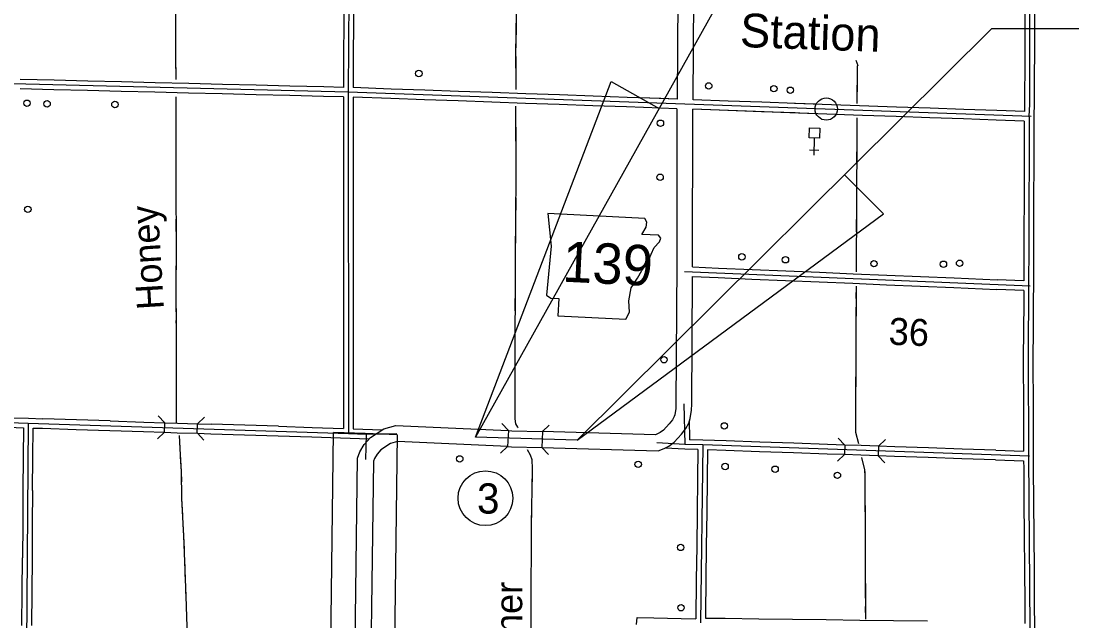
# Model space of a CAD drawing. Extents: x -4306 to 3843, y 131 to 8053.
# Drawn here: x -251 to 2383, y 4853 to 6356 of the extents above; entities that cross this region are included whole.
import ezdxf

# ---------------------------------------------------------------- set-up
doc = ezdxf.new("R2010")
doc.units = 0
for name, color, linetype in [('10', 7, 'Continuous'), ('21', 7, 'Continuous'), ('24', 7, 'Continuous'), ('31', 7, 'Continuous'), ('32', 7, 'Continuous'), ('37', 7, 'Continuous'), ('38', 7, 'Continuous'), ('43', 7, 'Continuous'), ('46', 7, 'Continuous'), ('5', 7, 'Continuous'), ('56', 7, 'Continuous'), ('57', 7, 'Continuous'), ('6', 7, 'Continuous'), ('R_No Plot', 7, 'Continuous')]:
    doc.layers.add(name, color=color, linetype=linetype)

msp = doc.modelspace()

# ---------------------------------------------------------------- linework, layer by layer
at = {"layer": '10'}
for p, q in [((1398.6, 6820.3), (1393.1, 6160.5)), ((1433.1, 6159.1), (1438.6, 6819.9)), ((1392.8, 6136.5), (1392.1, 5747.2)), ((1432, 5740.1), (1432.8, 6135.1)), ((1392.1, 5747.2), (1389.9, 5397.2)), ((1429.9, 5396.7), (1431.9, 5716.1)), ((1389.7, 5385.2), (1387.2, 5370.1)), ((1389.9, 5397.2), (1389.7, 5385.2)), ((1426.2, 5360.4), (1429.6, 5381.7)), ((1429.6, 5381.7), (1429.9, 5396.7)), ((1373.5, 5347), (1358.8, 5331.4)), ((1381.2, 5357.3), (1373.5, 5347)), ((1385.6, 5365.4), (1381.2, 5357.3)), ((1387.2, 5370.1), (1385.6, 5365.4)), ((1414.9, 5335.6), (1422.4, 5349.1)), ((1422.4, 5349.1), (1426.2, 5360.4)), ((970.3, 5330.2), (968.5, 5290.2)), ((970.2, 5330.2), (979.3, 5329.8)), ((979.3, 5329.8), (1055.4, 5327.7)), ((1055.5, 5327.7), (1054.4, 5287.7)), ((1338.9, 5319.9), (1055.4, 5327.7)), ((1344, 5321.7), (1338.9, 5319.9)), ((1350.7, 5325.3), (1344, 5321.7)), ((1358.8, 5331.4), (1350.7, 5325.3)), ((1385.6, 5301.5), (1404.2, 5321.2)), ((1404.2, 5321.2), (1414.9, 5335.6)), ((1372.3, 5291.4), (1385.6, 5301.5)), ((968.7, 5290.2), (977.9, 5289.8)), ((977.9, 5289.8), (1054.1, 5287.7)), ((1054.1, 5287.7), (1345.4, 5279.7)), ((1345.4, 5279.7), (1360.3, 5285.1)), ((1360.3, 5285.1), (1372.3, 5291.4))]:
    msp.add_line(p, q, dxfattribs=at)
for points in [[(581.8, 4463.7), (592.6, 5261.1), (598.4, 5277.4), (608.7, 5295.2), (624.9, 5312.8), (658.1, 5334.6), (688.3, 5342.8), (970.2, 5330.2)], [(968.7, 5290.2), (692.8, 5302.6), (674.8, 5297.7), (651, 5282.1), (641.1, 5271.4), (634.9, 5260.6), (632.5, 5254), (621.8, 4462.2)]]:
    msp.add_lwpolyline(points, dxfattribs=at)
at = {"layer": '21'}
msp.add_lwpolyline([(1069, 5873.9), (1077.2, 5792.2), (1065.8, 5669.4), (1076.3, 5662.1), (1096.6, 5661.2), (1094.5, 5617.9), (1264.8, 5609.6), (1273.8, 5626.7), (1272.5, 5655.3), (1278.1, 5687.5), (1294.2, 5712.5), (1304.6, 5730.9), (1319.1, 5750.6), (1328.3, 5771.8), (1335.9, 5789), (1348.8, 5803.3), (1352, 5812.6), (1346.9, 5819.7), (1305, 5821.7), (1315.4, 5840.2), (1317.3, 5852.3), (1312.2, 5861.9)], close=True, dxfattribs=at)
at = {"layer": '24'}
msp.add_circle((1766.9, 6135.8), 28, dxfattribs=at)
at = {"layer": '31'}
for p, q in [((-269.5, 5362), (-232.4, 5361)), ((-232.4, 5361), (-196.6, 5359.9)), ((-27.7, 5354.4), (56.7, 5351.7)), ((56.7, 5351.7), (109.5, 5350)), ((108.8, 5326.1), (109.5, 5350.1)), ((109.5, 5350), (141.2, 5349)), ((141.2, 5349), (191.7, 5347.4)), ((190.7, 5323.4), (191.5, 5347.4)), ((191.7, 5347.4), (225.6, 5346.3)), ((-281.8, 5338.4), (-244.9, 5337.3)), ((-220.9, 5336.6), (-197.4, 5335.9)), ((-28.5, 5330.4), (56, 5327.7)), ((56, 5327.7), (108.5, 5326)), ((108.5, 5326), (140.4, 5325)), ((140.4, 5325), (190.9, 5323.4)), ((190.9, 5323.4), (224.9, 5322.3)), ((394.5, 5340.9), (479, 5338.1)), ((479, 5338.1), (557.4, 5335.6)), ((581.4, 5334.9), (653.8, 5332.5)), ((393.7, 5316.9), (478.2, 5314.2)), ((478.2, 5314.2), (621.8, 5309.5)), ((-246.1, 5180.1), (-246.7, 5095.6)), ((-222.1, 5179.9), (-222.7, 5095.5)), ((-246.7, 5095.6), (-247.3, 5011.2)), ((-222.7, 5095.5), (-223.3, 5011))]:
    msp.add_line(p, q, dxfattribs=at)
for points in [[(-112.2, 5357.1), (-196.6, 5359.9)], [(-27.7, 5354.4), (-112.2, 5357.1)], [(310.1, 5343.6), (225.6, 5346.3)], [(-244.9, 5337.3), (-245.4, 5264.6)], [(-221.4, 5264.4), (-220.9, 5336.6)], [(-197.4, 5335.9), (-112.9, 5333.2)], [(-112.9, 5333.2), (-28.5, 5330.4)], [(224.9, 5322.3), (309.3, 5319.6)], [(394.5, 5340.9), (310.1, 5343.6)], [(309.3, 5319.6), (393.7, 5316.9)], [(-245.4, 5264.6), (-246.1, 5180.1)], [(-222.1, 5179.9), (-221.4, 5264.4)], [(-248, 4926.7), (-247.3, 5011.2)], [(-223.3, 5011), (-224, 4926.5)], [(-248.6, 4842.2), (-248, 4926.7)], [(-224, 4926.5), (-224.6, 4842)]]:
    msp.add_lwpolyline(points, dxfattribs=at)
at = {"layer": '32'}
for p, q in [((573.1, 7028.1), (569.1, 6177.8)), ((2276.5, 6530), (2276.2, 6245.5)), ((2276.5, 6530), (2276.2, 6245.5)), ((558.3, 6436.7), (557.9, 6352.2)), ((582.3, 6436.6), (581.9, 6352.1)), ((2264.4, 6418.9), (2264.3, 6334.5)), ((2288.4, 6418.9), (2288.3, 6334.4)), ((557.9, 6352.2), (557.5, 6267.8)), ((581.9, 6352.1), (581.5, 6267.6)), ((2264.3, 6334.5), (2264.2, 6250)), ((2288.3, 6334.4), (2288.3, 6249.9)), ((557.5, 6267.8), (557.1, 6190.1)), ((581.5, 6267.6), (581.1, 6189.4)), ((2264.2, 6245.5), (2264, 6165.5)), ((2264.2, 6250), (2264.2, 6245.5)), ((2276.2, 6245.5), (2276, 6146.8)), ((2276.2, 6245.5), (2276, 6146.8)), ((2288.2, 6245.5), (2288, 6165.4)), ((2288.3, 6249.9), (2288.2, 6245.5)), ((569.1, 6177.8), (-271.9, 6198.6)), ((-168.2, 6208), (-252.7, 6210.1)), ((-83.8, 6205.9), (-168.2, 6208)), ((0.7, 6203.8), (-83.8, 6205.9)), ((85.2, 6201.7), (0.7, 6203.8)), ((169.6, 6199.7), (85.2, 6201.7)), ((254.1, 6197.6), (169.6, 6199.7)), ((338.6, 6195.5), (254.1, 6197.6)), ((423, 6193.4), (338.6, 6195.5)), ((507.5, 6191.3), (423, 6193.4)), ((557.1, 6190.1), (507.5, 6191.3)), ((676.5, 6186), (581.1, 6189.4)), ((-168.8, 6184), (-253.3, 6186.1)), ((-84.4, 6181.9), (-168.8, 6184)), ((0.1, 6179.8), (-84.4, 6181.9)), ((84.6, 6177.7), (0.1, 6179.8)), ((169, 6175.7), (84.6, 6177.7)), ((253.5, 6173.6), (169, 6175.7)), ((338, 6171.5), (253.5, 6173.6)), ((422.4, 6169.4), (338, 6171.5)), ((506.9, 6167.3), (422.4, 6169.4)), ((557.1, 6166.1), (506.9, 6167.3)), ((557.1, 6166.1), (557.1, 6098.7)), ((569.1, 6177.8), (569.4, 5323.2)), ((2280.4, 6116.9), (569.1, 6177.8)), ((581.1, 6165.3), (581.1, 6098.7)), ((675.7, 6162), (581.1, 6165.3)), ((760.9, 6183), (676.5, 6186)), ((845.4, 6180), (760.9, 6183)), ((929.8, 6177), (845.4, 6180)), ((1014.2, 6174), (929.8, 6177)), ((1098.7, 6171), (1014.2, 6174)), ((1183.1, 6168), (1098.7, 6171)), ((1267.6, 6164.9), (1183.1, 6168)), ((1352, 6161.9), (1267.6, 6164.9)), ((1393.1, 6160.5), (1302, 6163.7)), ((1393.1, 6160.5), (1302, 6163.7)), ((2264, 6165.5), (2264, 6129.7)), ((2288, 6165.4), (2288, 6146.5)), ((760.1, 6159), (675.7, 6162)), ((844.5, 6156), (760.1, 6159)), ((929, 6153), (844.5, 6156)), ((1013.4, 6150), (929, 6153)), ((1097.8, 6147), (1013.4, 6150)), ((1182.3, 6144), (1097.8, 6147)), ((1266.7, 6141), (1182.3, 6144)), ((1351.1, 6138), (1266.7, 6141)), ((1392.8, 6136.5), (1351.1, 6138)), ((1393.1, 6160.5), (1352, 6161.9)), ((1520.9, 6155.9), (1433.1, 6159.1)), ((1605.3, 6152.9), (1520.9, 6155.9)), ((1689.7, 6149.9), (1605.3, 6152.9)), ((1943, 6140.9), (1687.3, 6150)), ((1741.7, 6148.1), (1687.3, 6150)), ((2027.5, 6137.9), (1943, 6140.9)), ((2111.9, 6134.9), (2027.5, 6137.9)), ((2276, 6146.8), (2274.8, 6117.7)), ((2276, 6146.8), (2274.8, 6117.7)), ((2288, 6146.5), (2287, 6121.8)), ((1741.5, 6124.1), (1432.8, 6135.1)), ((1857.8, 6119.9), (1432.8, 6135.1)), ((1520, 6132), (1432.8, 6135.1)), ((1604.4, 6128.9), (1520, 6132)), ((1688.9, 6125.9), (1604.4, 6128.9)), ((1942.2, 6116.9), (1857.8, 6119.9)), ((2026.6, 6113.9), (1942.2, 6116.9)), ((2111.1, 6110.9), (2026.6, 6113.9)), ((2192.5, 6108.2), (2111.1, 6110.9)), ((2194.1, 6132.2), (2111.9, 6134.9)), ((2264, 6129.7), (2194, 6132.2)), ((2275, 6114), (2274.1, 5793.5)), ((2275, 6114), (2274.1, 5793.5)), ((2274.8, 6117.7), (2275, 6114)), ((2274.8, 6117.7), (2275, 6114)), ((2287, 6121.8), (2286.9, 6081)), ((557.1, 6098.7), (557.1, 6014.2)), ((581.1, 6098.7), (581.1, 6014.2)), ((2262.9, 6105.7), (2192.6, 6108.3)), ((2262.9, 6105.7), (2262.7, 5996.6)), ((2286.9, 6081), (2286.7, 5996.5)), ((557.1, 6014.2), (557.2, 5929.7)), ((581.1, 6014.2), (581.2, 5929.7)), ((2262.7, 5996.6), (2262.4, 5912.1)), ((2286.7, 5996.5), (2286.4, 5912)), ((557.2, 5929.7), (557.2, 5845.2)), ((581.2, 5929.7), (581.2, 5845.3)), ((2262.4, 5912.1), (2262.2, 5827.6)), ((2286.4, 5912), (2286.2, 5827.5)), ((557.2, 5845.2), (557.2, 5760.8)), ((581.2, 5845.3), (581.3, 5760.8)), ((2262.2, 5827.6), (2262.1, 5793.5)), ((2286.2, 5827.5), (2286.1, 5793.5)), ((2262.1, 5793.5), (2262, 5743.1)), ((2274.1, 5793.5), (2273.8, 5693.1)), ((2274.1, 5793.5), (2273.8, 5693.1)), ((2286.1, 5793.5), (2286, 5743)), ((557.2, 5760.8), (557.3, 5676.3)), ((581.3, 5760.8), (581.3, 5676.3)), ((2262, 5743.1), (2261.9, 5705.1)), ((2286, 5743), (2285.8, 5693.1)), ((1411.9, 5728.9), (2278.2, 5692.6)), ((1431.9, 5716.1), (1495.8, 5713.4)), ((1432, 5740.1), (1496.8, 5737.4)), ((1496.8, 5737.4), (1581.2, 5733.8)), ((1581.2, 5733.8), (1665.6, 5730.3)), ((1665.6, 5730.3), (1750.1, 5726.8)), ((1750.1, 5726.8), (1834.5, 5723.2)), ((1834.5, 5723.2), (1918.9, 5719.7)), ((1918.9, 5719.7), (2003.3, 5716.1)), ((2003.3, 5716.1), (2087.7, 5712.6)), ((1495.8, 5713.4), (1580.2, 5709.9)), ((1580.2, 5709.9), (1664.6, 5706.3)), ((1664.6, 5706.3), (1749.1, 5702.8)), ((1749.1, 5702.8), (1833.5, 5699.2)), ((1833.5, 5699.2), (1917.9, 5695.7)), ((1917.9, 5695.7), (2002.3, 5692.2)), ((2002.3, 5692.2), (2086.7, 5688.6)), ((2086.7, 5688.6), (2194.4, 5683.9)), ((2087.7, 5712.6), (2195.4, 5707.9)), ((2261.9, 5705.1), (2195.4, 5707.9)), ((2273.8, 5693.1), (2272.6, 5518.6)), ((2273.8, 5693.1), (2272.6, 5518.6)), ((2285.8, 5693.1), (2285.6, 5658.5)), ((557.3, 5676.3), (557.3, 5591.8)), ((581.3, 5676.3), (581.3, 5591.8)), ((2261.8, 5681.1), (2194.4, 5683.9)), ((2261.8, 5681.1), (2261.6, 5658.6)), ((2261.6, 5658.6), (2261, 5574.2)), ((2285.6, 5658.5), (2285, 5574)), ((557.3, 5591.8), (557.4, 5507.3)), ((581.3, 5591.8), (581.4, 5507.3)), ((2261, 5574.2), (2260.6, 5518.6)), ((2285, 5574), (2284.6, 5518.6)), ((557.4, 5507.3), (557.4, 5422.8)), ((581.4, 5507.3), (581.4, 5422.8)), ((2260.6, 5518.6), (2260.7, 5489.6)), ((2272.6, 5518.6), (2273.4, 5266)), ((2272.6, 5518.6), (2273.4, 5266)), ((2284.6, 5518.6), (2284.7, 5489.6)), ((2260.7, 5489.6), (2261, 5405.1)), ((2284.7, 5489.6), (2285, 5405.1)), ((557.4, 5422.8), (557.4, 5335.6)), ((581.4, 5422.8), (581.4, 5334.9)), ((2261, 5405.1), (2261.2, 5320.6)), ((2285, 5405.1), (2285.2, 5320.7)), ((1409.9, 5396.9), (1412.9, 5295.6)), ((-281.4, 5350.4), (-232.8, 5349)), ((-232.8, 5349), (-239.3, 4486.5)), ((-232.8, 5349), (569.4, 5323.2)), ((1423.2, 5352.9), (1424.4, 5312.8)), ((569.4, 5323.2), (613.9, 5321.6)), ((613.9, 5321.6), (612.6, 5257.5)), ((613.9, 5321.6), (690.6, 5322.7)), ((2261.2, 5320.6), (2261.4, 5278.7)), ((2285.2, 5320.7), (2285.4, 5266.1)), ((1412.9, 5295.6), (1342.1, 5299.8)), ((1457.4, 5294.3), (1412.9, 5295.6)), ((1424.4, 5312.8), (1424.6, 5307.2)), ((1457.8, 5306.3), (1424.6, 5307.2)), ((1457.4, 5294.3), (1451.8, 4848.8)), ((2275.9, 5266), (1457.4, 5294.3)), ((1516.4, 5304.2), (1457.8, 5306.2)), ((1600.8, 5301.3), (1516.4, 5304.2)), ((1685.3, 5298.4), (1600.8, 5301.3)), ((1769.7, 5295.5), (1685.3, 5298.4)), ((1813.2, 5294), (1769.7, 5295.5)), ((1813.2, 5294), (1812.3, 5270)), ((1854.1, 5292.6), (1813.2, 5294)), ((1412.4, 5283.6), (1362.9, 5286.5)), ((1445.3, 5282.6), (1412.4, 5283.6)), ((1445.3, 5282.6), (1444.4, 5209.9)), ((1469.3, 5281.8), (1468.4, 5209.6)), ((1515.5, 5280.2), (1469.3, 5281.8)), ((1600, 5277.3), (1515.5, 5280.2)), ((1684.4, 5274.4), (1600, 5277.3)), ((1768.9, 5271.5), (1684.4, 5274.4)), ((1812.3, 5270), (1768.9, 5271.5)), ((1853.3, 5268.6), (1812.3, 5270)), ((1897.3, 5267.1), (1853.3, 5268.6)), ((1898.1, 5291.1), (1854.1, 5292.6)), ((1898.1, 5291.1), (1897.3, 5267.1)), ((1938.6, 5289.7), (1898.1, 5291.1)), ((2023, 5286.7), (1938.6, 5289.7)), ((2107.4, 5283.8), (2023, 5286.7)), ((2191.8, 5281.1), (2107.4, 5283.8)), ((2191.8, 5281.1), (2261.4, 5278.7)), ((1937.7, 5265.7), (1897.3, 5267.1)), ((2022.2, 5262.8), (1937.7, 5265.7)), ((2106.6, 5259.8), (2022.2, 5262.8)), ((2191, 5257.2), (2106.6, 5259.8)), ((2191, 5257.2), (2261.5, 5254.7)), ((2261.5, 5254.7), (2261.6, 5236)), ((2273.4, 5266), (2276.7, 4834.6)), ((2273.4, 5266), (2276.7, 4834.6)), ((2285.4, 5266.1), (2285.6, 5236.2)), ((2261.6, 5236), (2262.3, 5151.5)), ((2285.6, 5236.2), (2286.3, 5151.7)), ((1444.4, 5209.9), (1443.3, 5125.4)), ((1468.4, 5209.6), (1467.3, 5125.1)), ((2262.3, 5151.5), (2262.9, 5067.1)), ((2286.3, 5151.7), (2286.9, 5067.2)), ((1443.3, 5125.4), (1442.2, 5041)), ((1467.3, 5125.1), (1466.2, 5040.7)), ((2262.9, 5067.1), (2263.6, 4982.6)), ((2286.9, 5067.2), (2287.6, 4982.8)), ((1442.2, 5041), (1441.1, 4956.5)), ((1466.2, 5040.7), (1465.1, 4956.2)), ((2263.6, 4982.6), (2264.2, 4898.1)), ((2287.6, 4982.8), (2288.2, 4898.3)), ((1441.1, 4956.5), (1439.9, 4858.8)), ((1465.1, 4956.2), (1464.1, 4871.7)), ((2264.2, 4898.1), (2264.6, 4846.6)), ((2288.2, 4898.3), (2288.7, 4834.6)), ((1464.1, 4871.7), (1463.9, 4860.6)), ((1463.9, 4860.6), (1513.3, 4859.9)), ((1513.3, 4859.9), (1597.8, 4858.8)), ((1597.8, 4858.8), (1682.3, 4857.7)), ((1682.3, 4857.7), (1766.8, 4856.6)), ((1766.8, 4856.6), (1851.2, 4855.5)), ((1851.2, 4855.5), (1935.7, 4854.4)), ((1935.7, 4854.4), (2020.2, 4853.2))]:
    msp.add_line(p, q, dxfattribs=at)
at = {"layer": '37'}
for p, q in [((969.4, 5310.2), (969.4, 5310.2)), ((1054.9, 5307.7), (1054.9, 5307.7))]:
    msp.add_line(p, q, dxfattribs=at)
for points in [[(970.3, 5330.2), (954.1, 5347.9)], [(1072.9, 5344.2), (1055.5, 5327.7)], [(950.8, 5274), (968.5, 5290.2)], [(1054.4, 5287.7), (1070.9, 5270.2)]]:
    msp.add_lwpolyline(points, dxfattribs=at)
at = {"layer": '38'}
for points in [[(92.9, 5367.5), (109.3, 5350)], [(191.7, 5347.4), (209.2, 5363.8)], [(108.5, 5326), (91, 5309.6)], [(207.3, 5305.9), (190.9, 5323.4)], [(1796.8, 5311.5), (1813.2, 5294)], [(1898.1, 5291.1), (1915.6, 5307.5)], [(1812.3, 5270), (1794.8, 5253.6)], [(1913.7, 5249.5), (1897.3, 5267.1)]]:
    msp.add_lwpolyline(points, dxfattribs=at)
at = {"layer": '43'}
for points in [[(137, 7010.5), (136.7, 6978.4), (137.2, 6875.4), (136.8, 6800.3), (136.9, 6727.5), (136.9, 6612.5), (136.7, 6457.1), (136.1, 6359.3), (136, 6263.3), (137.2, 6210)], [(990.8, 6996.5), (990.7, 6986.2), (991, 6793.8), (990.1, 6688.9), (989.1, 6602.1), (990.1, 6491.2), (989.9, 6377.6), (988.5, 6273.2), (989.3, 6201.9), (988.9, 6184.6)], [(136.1, 6366.2), (136.1, 6359.3), (136, 6302.9)], [(989.6, 6352.3), (988.7, 6288.9)], [(136, 6281.7), (136, 6263.3), (137, 6218.4)], [(988.6, 6267.8), (989.3, 6204.4)], [(1841.2, 6258.1), (1845.8, 6244.8), (1844.7, 6243.1), (1843.9, 6149.8)], [(1841.2, 6258.1), (1845.8, 6244.8), (1844.7, 6243.1), (1844.5, 6227.5)], [(1844.4, 6206.3), (1843.9, 6149.8)], [(137.2, 6166.1), (137.1, 6057.3), (136.7, 5955.8), (137.5, 5782.3), (136.8, 5681.7), (137.5, 5591.2), (138.2, 5550.4), (138, 5431.7), (137.9, 5349.1)], [(137.2, 6166.1), (137.1, 6134.5)], [(988.4, 6143.3), (989.1, 5966.3)], [(988.4, 6143.3), (988.5, 6111.6)], [(137.1, 6113.3), (137.1, 6057.3), (137, 6050)], [(1843.6, 6113.5), (1843.2, 6070.2), (1841.7, 5727.9)], [(1843.6, 6113.5), (1843.3, 6081.8)], [(988.6, 6090.5), (988.9, 6027.1)], [(1843.2, 6060.7), (1842.9, 5997.3)], [(137, 6028.8), (136.8, 5965.5)], [(988.9, 6006), (989.1, 5966.3)], [(989.1, 5966.3), (987.4, 5768.6), (987.2, 5746.5)], [(989.1, 5966.3), (988.8, 5934.6)], [(1842.8, 5976.2), (1842.5, 5912.8)], [(136.8, 5944.4), (137.1, 5881)], [(988.6, 5913.5), (988.1, 5850.1)], [(1842.4, 5891.7), (1842.2, 5828.3)], [(137.2, 5859.9), (137.5, 5796.5)], [(987.9, 5829), (987.4, 5768.6), (987.3, 5765.7)], [(1842.1, 5807.2), (1841.8, 5743.8)], [(137.5, 5775.4), (137, 5712)], [(987.2, 5746.5), (986.2, 5491.9), (986.4, 5359.4), (988, 5347.3), (992.9, 5338.6), (993.9, 5336.8)], [(987.2, 5746.5), (987, 5714.8)], [(136.9, 5690.9), (136.8, 5681.7), (137, 5659.2)], [(987, 5693.7), (986.7, 5630.4)], [(1841.6, 5692.4), (1840.2, 5389.5), (1840.4, 5326.3), (1847.8, 5298.2)], [(1841.6, 5692.4), (1841.4, 5660.8)], [(137, 5659.2), (137.2, 5627.5)], [(1841.3, 5639.6), (1841.1, 5576.3)], [(137.3, 5606.4), (137.5, 5591.2), (138.2, 5550.4), (138.2, 5543)], [(986.6, 5609.2), (986.4, 5545.9)], [(1841, 5555.2), (1840.7, 5491.8)], [(138.2, 5521.9), (138.1, 5458.6)], [(986.3, 5524.7), (986.2, 5491.9), (986.2, 5461.4)], [(1840.6, 5470.7), (1840.3, 5407.3)], [(138, 5437.4), (138, 5431.7), (137.9, 5374.1)], [(986.2, 5440.3), (986.3, 5376.9)], [(1840.2, 5386.2), (1840.4, 5326.3), (1841.3, 5322.9)], [(145, 5317.6), (147, 5284.2), (150.3, 5227.5), (151.6, 5159.7), (156.3, 5066.2), (161.9, 4915.7), (165.2, 4812.6), (170.9, 4701), (174.9, 4602.5), (179.8, 4480.8)], [(145, 5317.6), (146.9, 5285.9)], [(1017.4, 5282.9), (1025.1, 5269.5), (1029.4, 5258.2), (1029.6, 5234.1), (1027.7, 5087.5), (1026.4, 4887), (1026.8, 4858.6), (1022.2, 4580.9), (1020.1, 4448.8)], [(1017.4, 5282.9), (1025.1, 5269.5), (1029.4, 5258.2), (1029.5, 5254)], [(148.1, 5264.9), (150.3, 5227.5), (150.8, 5201.6)], [(1865.8, 4857.8), (1864.5, 5216.2), (1863.8, 5232), (1856.4, 5262.8)], [(1029.6, 5232.9), (1028.8, 5169.6)], [(1864.7, 5164), (1864.5, 5216.2), (1864, 5227.4)], [(151.2, 5180.4), (151.6, 5159.7), (153.7, 5117.1)], [(1028.5, 5148.4), (1027.7, 5087.5), (1027.7, 5085.1)], [(1865, 5079.5), (1864.8, 5142.9)], [(154.8, 5096), (156.3, 5066.2), (157.6, 5032.7)], [(1027.6, 5064), (1027.2, 5000.6)], [(1865.3, 4995.1), (1865.1, 5058.4)], [(158.3, 5011.6), (160.7, 4948.3)], [(1027, 4979.5), (1026.6, 4916.1)], [(1865.6, 4910.6), (1865.4, 4973.9)], [(161.5, 4927.2), (161.9, 4915.7), (163.6, 4863.9)], [(1026.4, 4895), (1026.4, 4887), (1026.8, 4858.6), (1026.3, 4831.6)], [(1865.8, 4857.8), (1865.6, 4889.4)]]:
    msp.add_lwpolyline(points, dxfattribs=at)
at = {"layer": '46'}
for p, q in [((1291.7, 4844.6), (1293.3, 4862)), ((1293.3, 4862), (1334.8, 4860.9)), ((1334.8, 4860.9), (1403.3, 4859.2)), ((1403.3, 4859.2), (1439.9, 4858.8))]:
    msp.add_line(p, q, dxfattribs=at)
at = {"layer": '56'}
for centre in [(745.9, 6224.9), (1472.4, 6193.7), (1635.6, 6186.9), (1676.8, 6183), (-236, 6150.4), (-185.7, 6148.8), (-15.6, 6147.2), (1351.3, 6100.3), (1350.6, 5964.9), (-233.9, 5884.5), (1555.4, 5765.5), (1664.6, 5758.2), (1886.5, 5748.5), (2060.5, 5747), (2101, 5749.4), (1360.3, 5507.7), (1511.4, 5342), (848.4, 5259.3), (1295.6, 5245.6), (1513.4, 5240.3), (1638.7, 5233.4), (1794.8, 5218.2), (1402.1, 5037.5), (1402.9, 4886.4)]:
    msp.add_circle(centre, 8, dxfattribs=at)
at = {"layer": '57'}
for p, q in [((1736.3, 6020.2), (1737.1, 6063.2)), ((1748.5, 6031.9), (1724.5, 6032.4))]:
    msp.add_line(p, q, dxfattribs=at)
msp.add_lwpolyline([(1750.5, 6088), (1750.1, 6063), (1724.2, 6063.4), (1724.6, 6088.4)], close=True, dxfattribs=at)
at = {"layer": '6'}
for p, q in [((521.1, 4478.6), (532, 5325.5)), ((611.3, 5322.8), (532, 5325.5)), ((691.9, 5319.8), (611.3, 5322.8)), ((691.9, 5319.8), (680.9, 4470.6))]:
    msp.add_line(p, q, dxfattribs=at)
at = {"layer": 'R_No Plot'}
for p, q in [((1913.7, 7148.4), (887.6, 5313.5)), ((2181.1, 6337.1), (1143.1, 5305.9)), ((3842.8, 6337.1), (2181.1, 6337.1)), ((887.6, 5313.5), (1227.7, 6204.9)), ((1227.7, 6204.9), (1348.4, 6137.4)), ((1910.3, 5873.2), (1812.8, 5971.3)), ((1143.1, 5305.9), (1910.3, 5873.2)), ((1143.1, 5305.9), (887.6, 5313.5))]:
    msp.add_line(p, q, dxfattribs=at)
msp.add_circle((912.7, 5160.9), 68.6, dxfattribs=at)

# ---------------------------------------------------------------- texts
at = {"layer": '21'}
msp.add_text('139', height=101.29, rotation=357.2006, dxfattribs=at).set_placement((1104, 5703.5))
at = {"layer": '24'}
msp.add_text('Station', height=84.49, rotation=357.963, dxfattribs=at).set_placement((1549.9, 6291.5))
at = {"layer": '43'}
for s, rotation, p in [('Honey', 93.4261, (107.4, 5635)), ('Asher', 89.7677, (1004.3, 4715))]:
    msp.add_text(s, height=67.59, rotation=rotation, dxfattribs=at).set_placement(p)
at = {"layer": '5'}
msp.add_text('36', height=67.59, rotation=357.6004, dxfattribs=at).set_placement((1922.4, 5545.7))
at = {"layer": 'R_No Plot'}
msp.add_text('3', height=75.7, dxfattribs=at).set_placement((891.7, 5122.3))

doc.saveas('drawing.dxf')
